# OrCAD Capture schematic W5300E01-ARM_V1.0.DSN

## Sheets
1 P1. MPU, Jtag Interface: size C; rev: 1.0
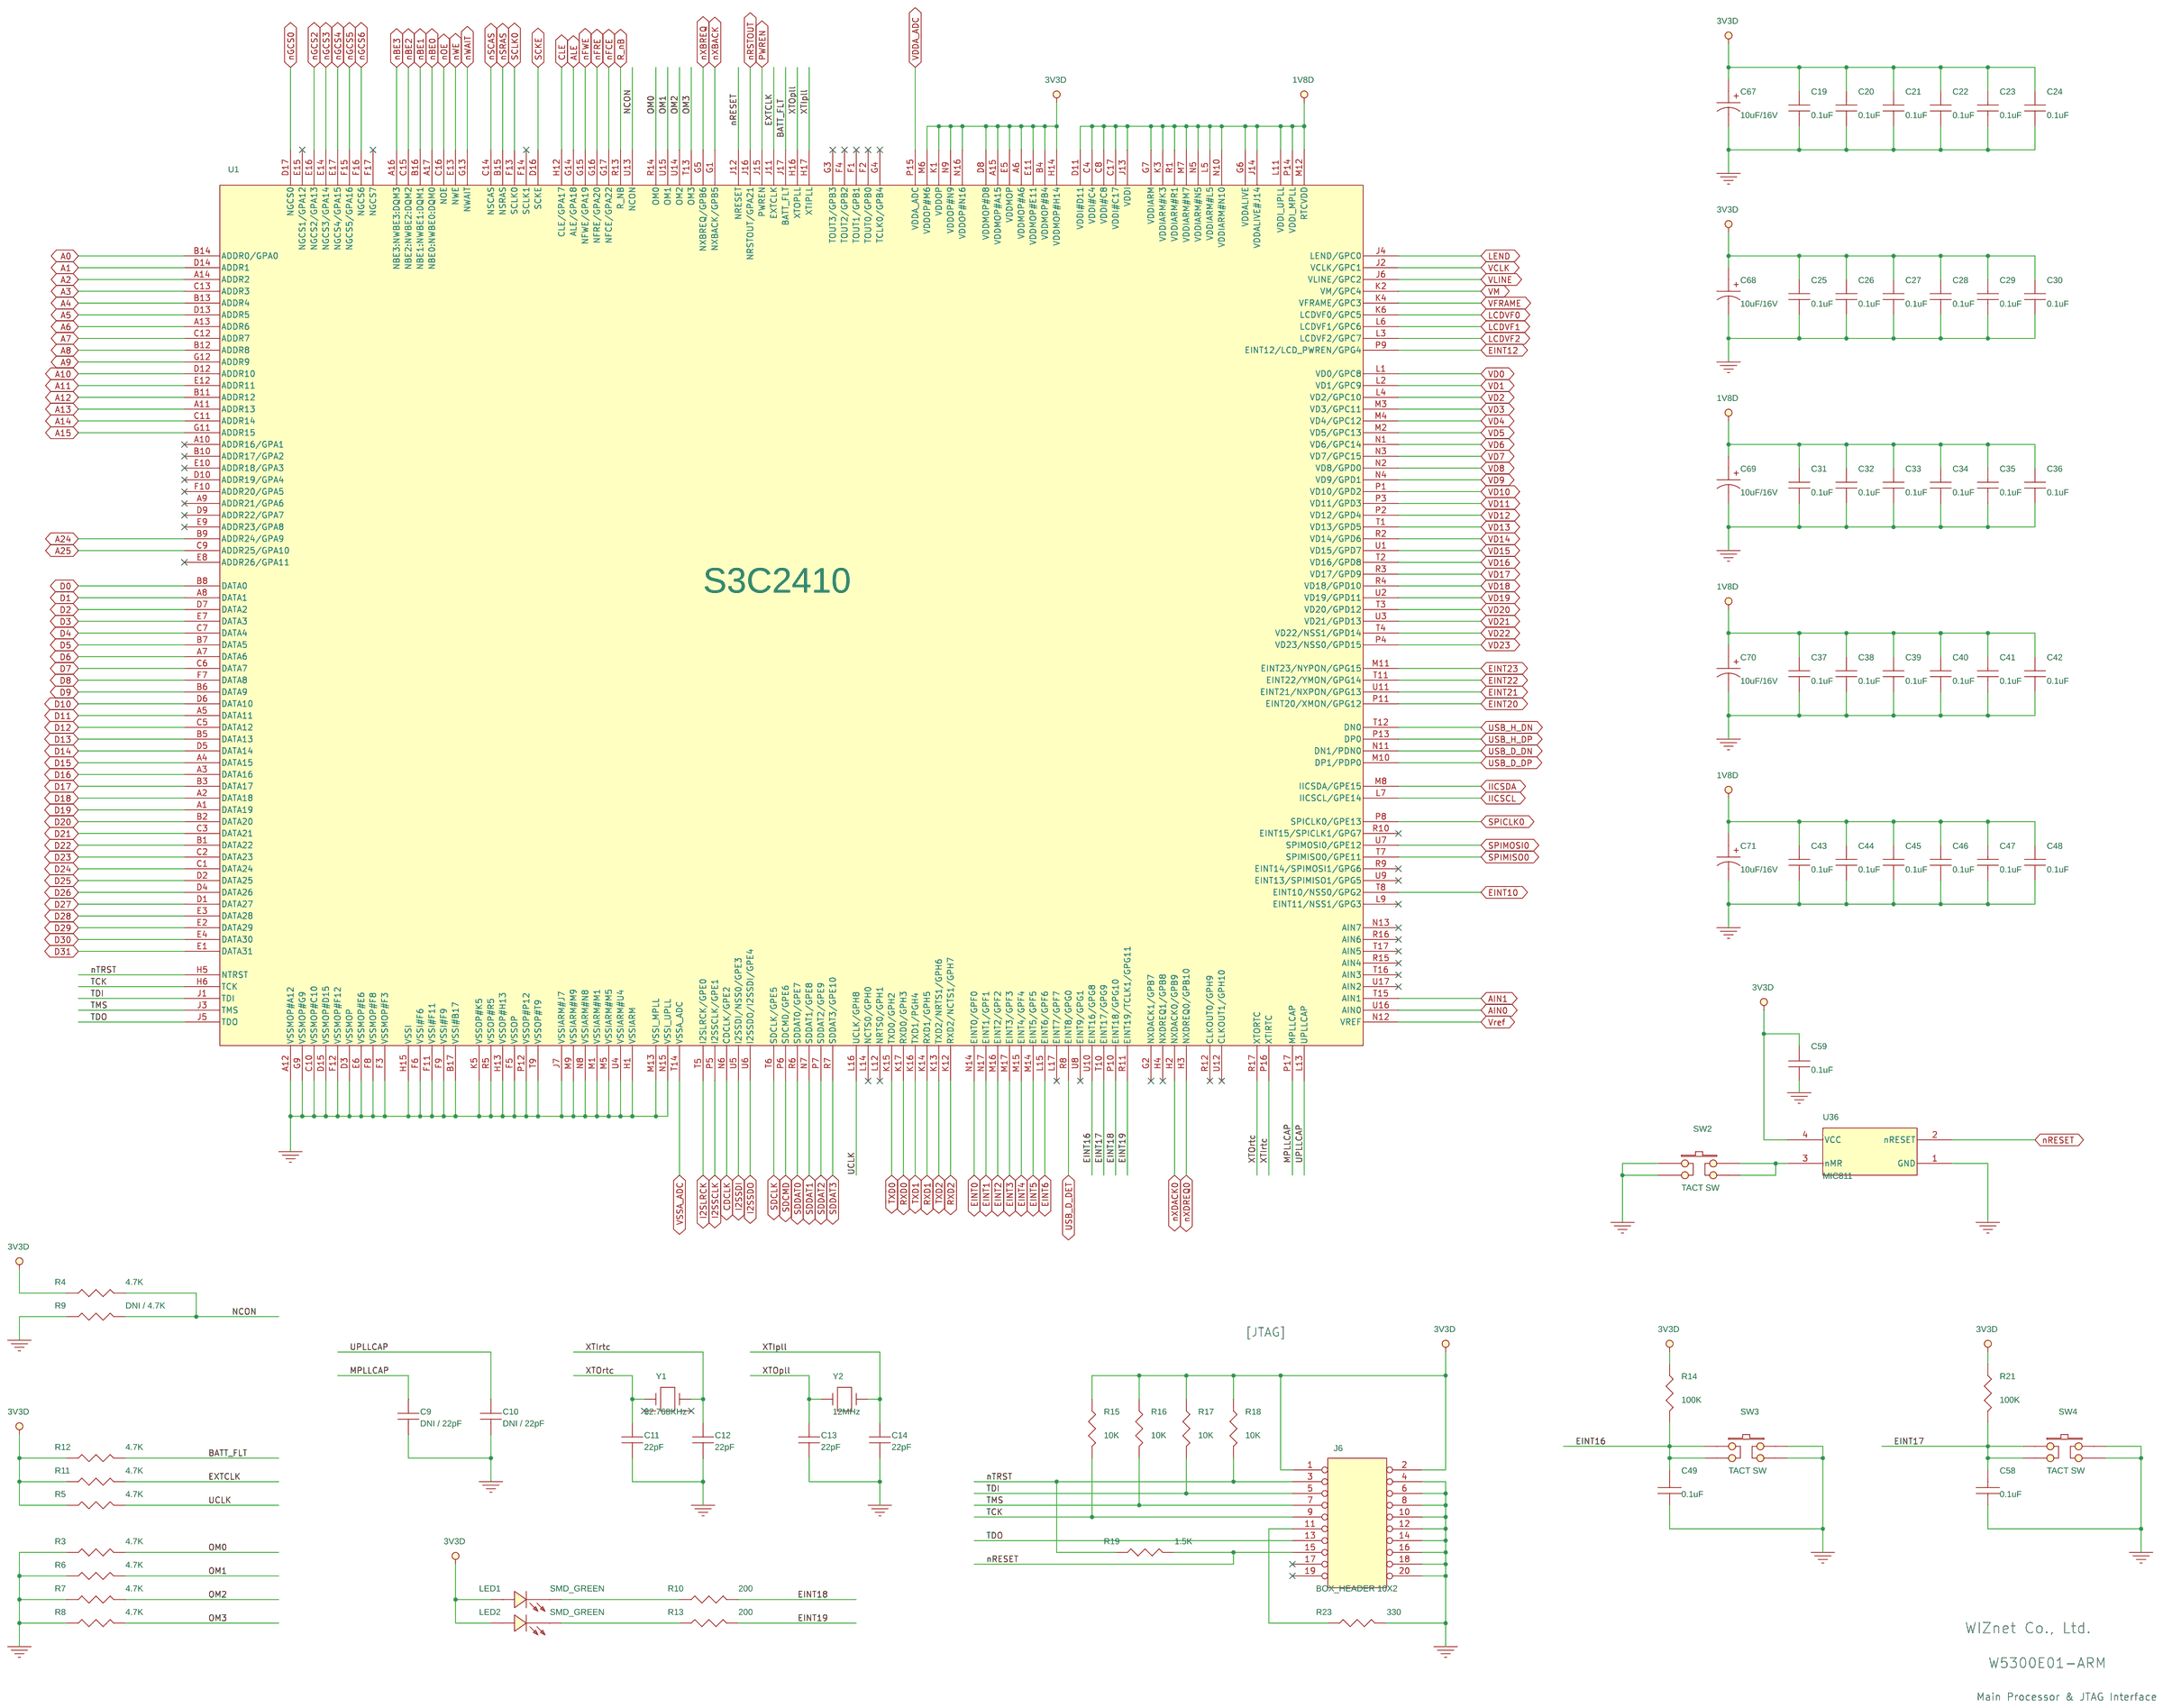
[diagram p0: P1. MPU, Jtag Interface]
2 LAYOUT
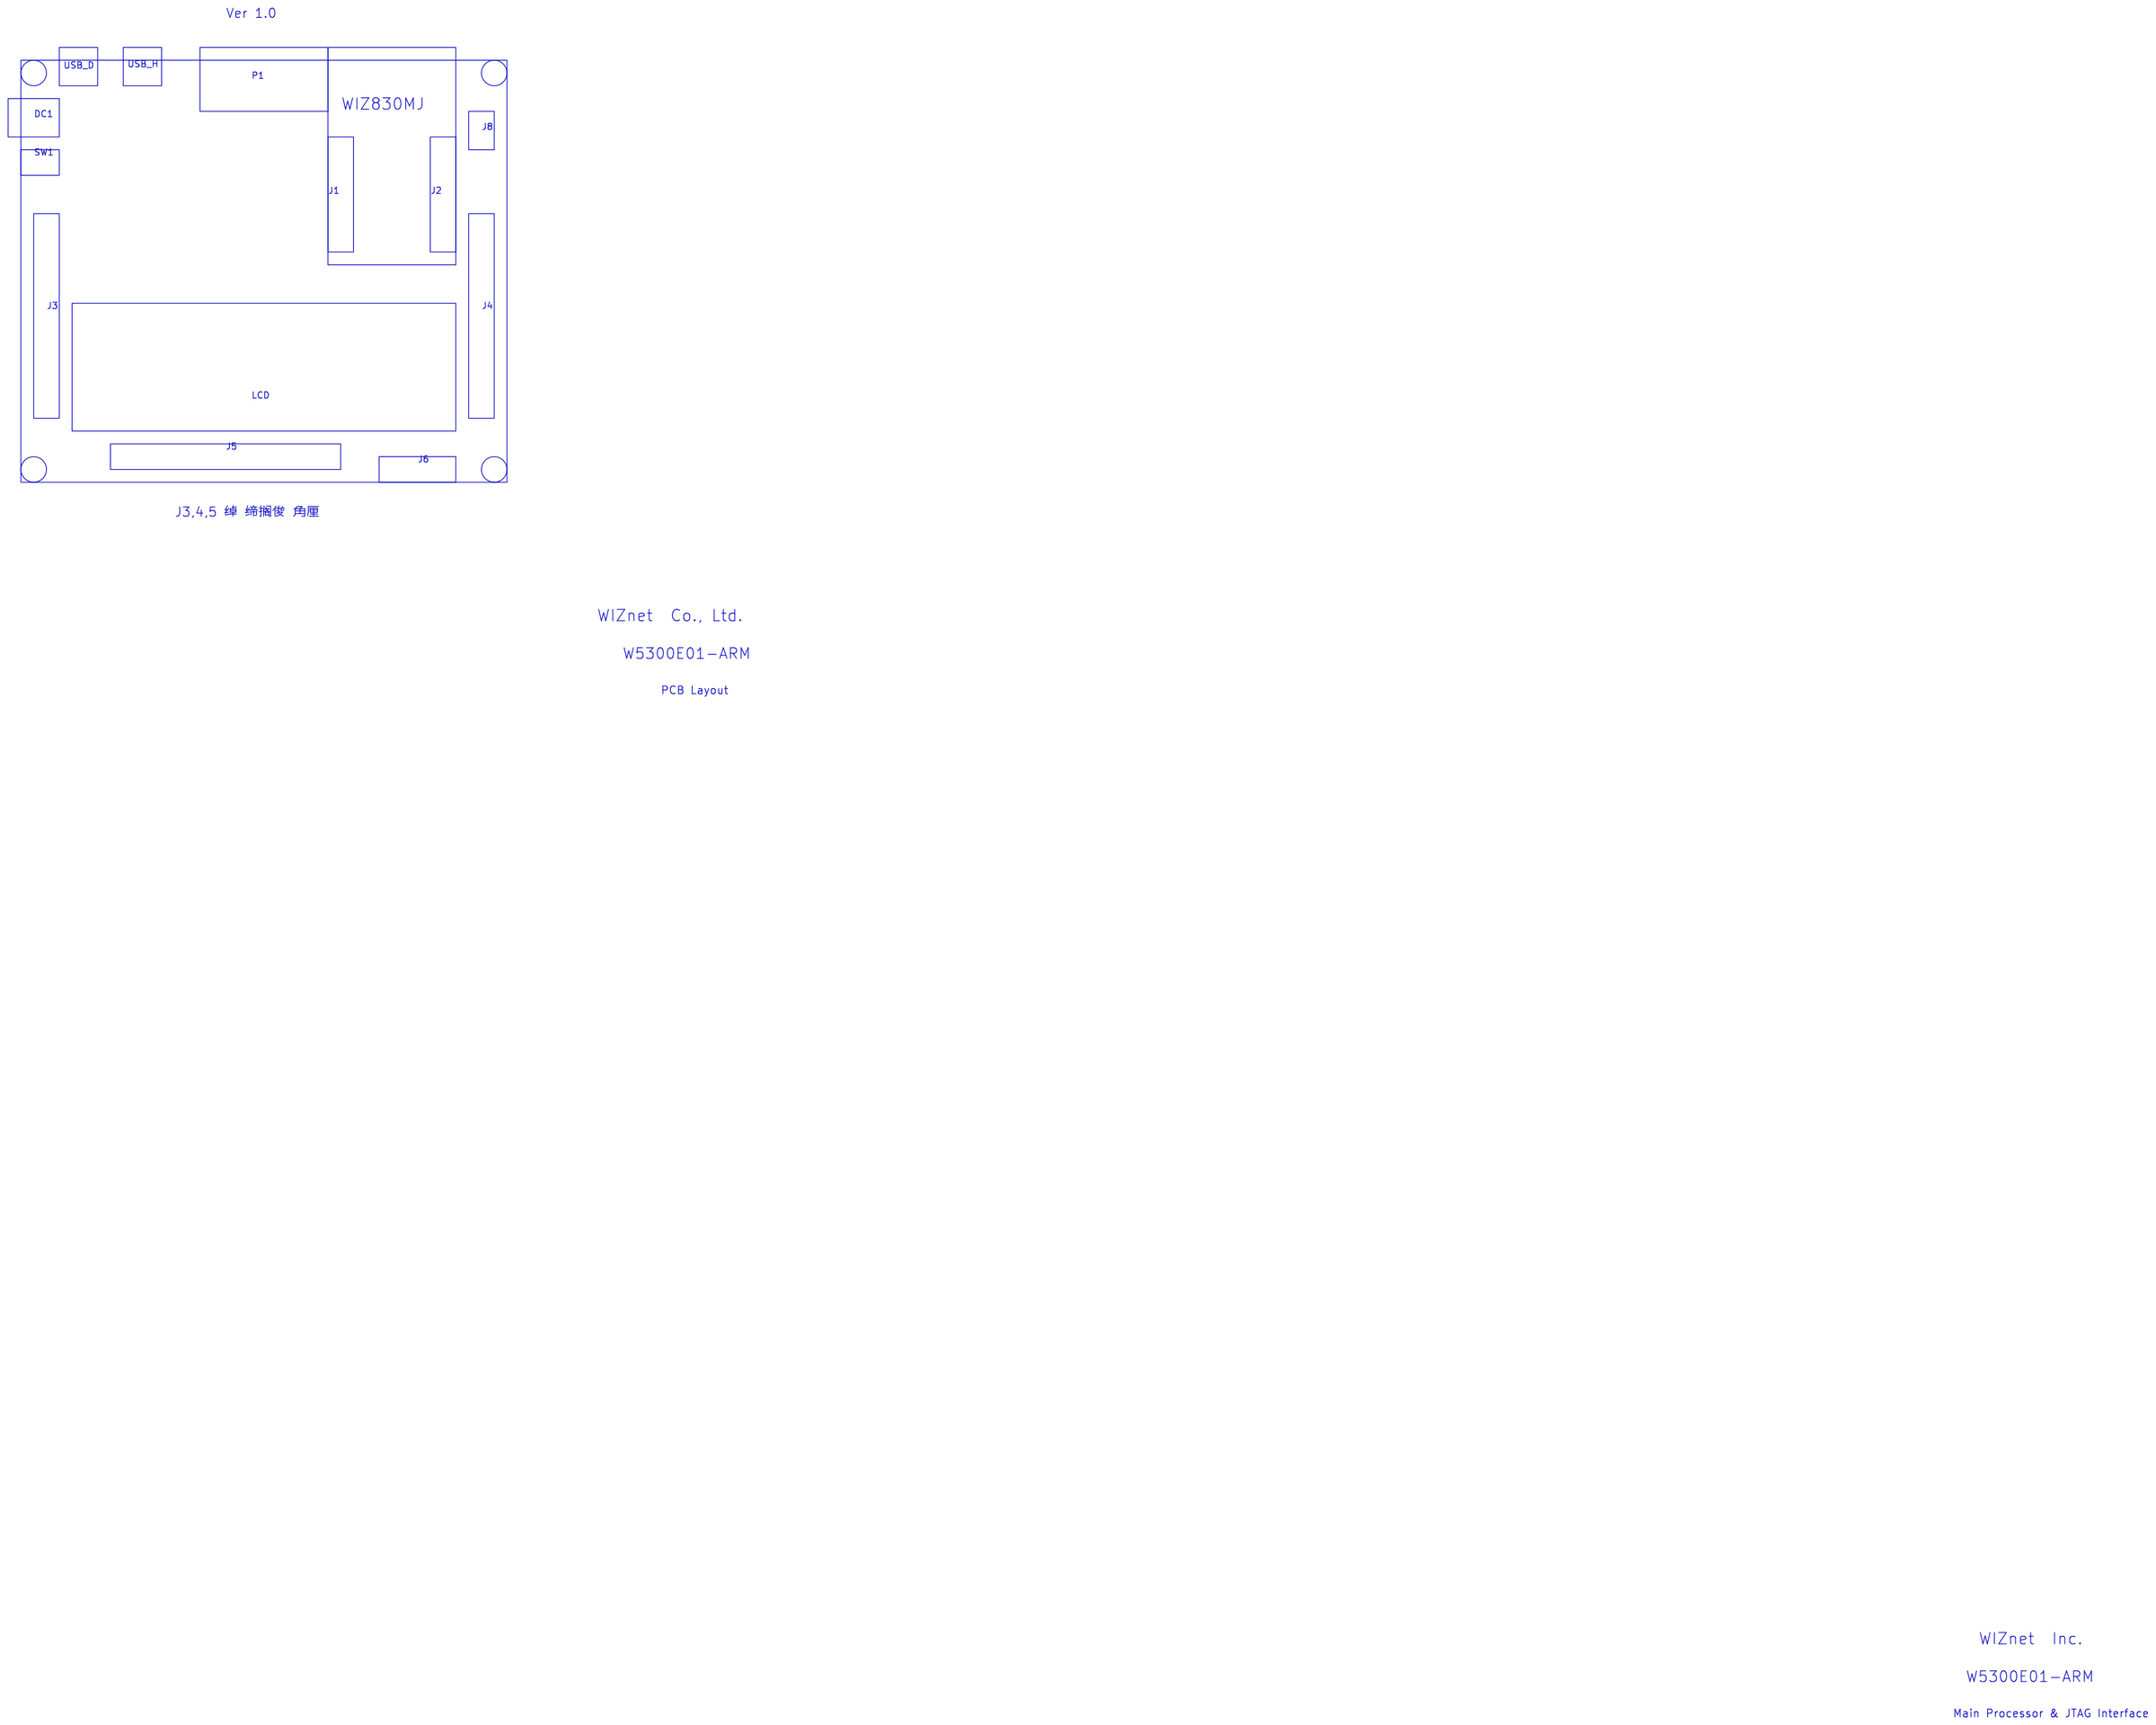
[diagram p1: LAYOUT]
3 P2. Momory, I/O, Power: size C
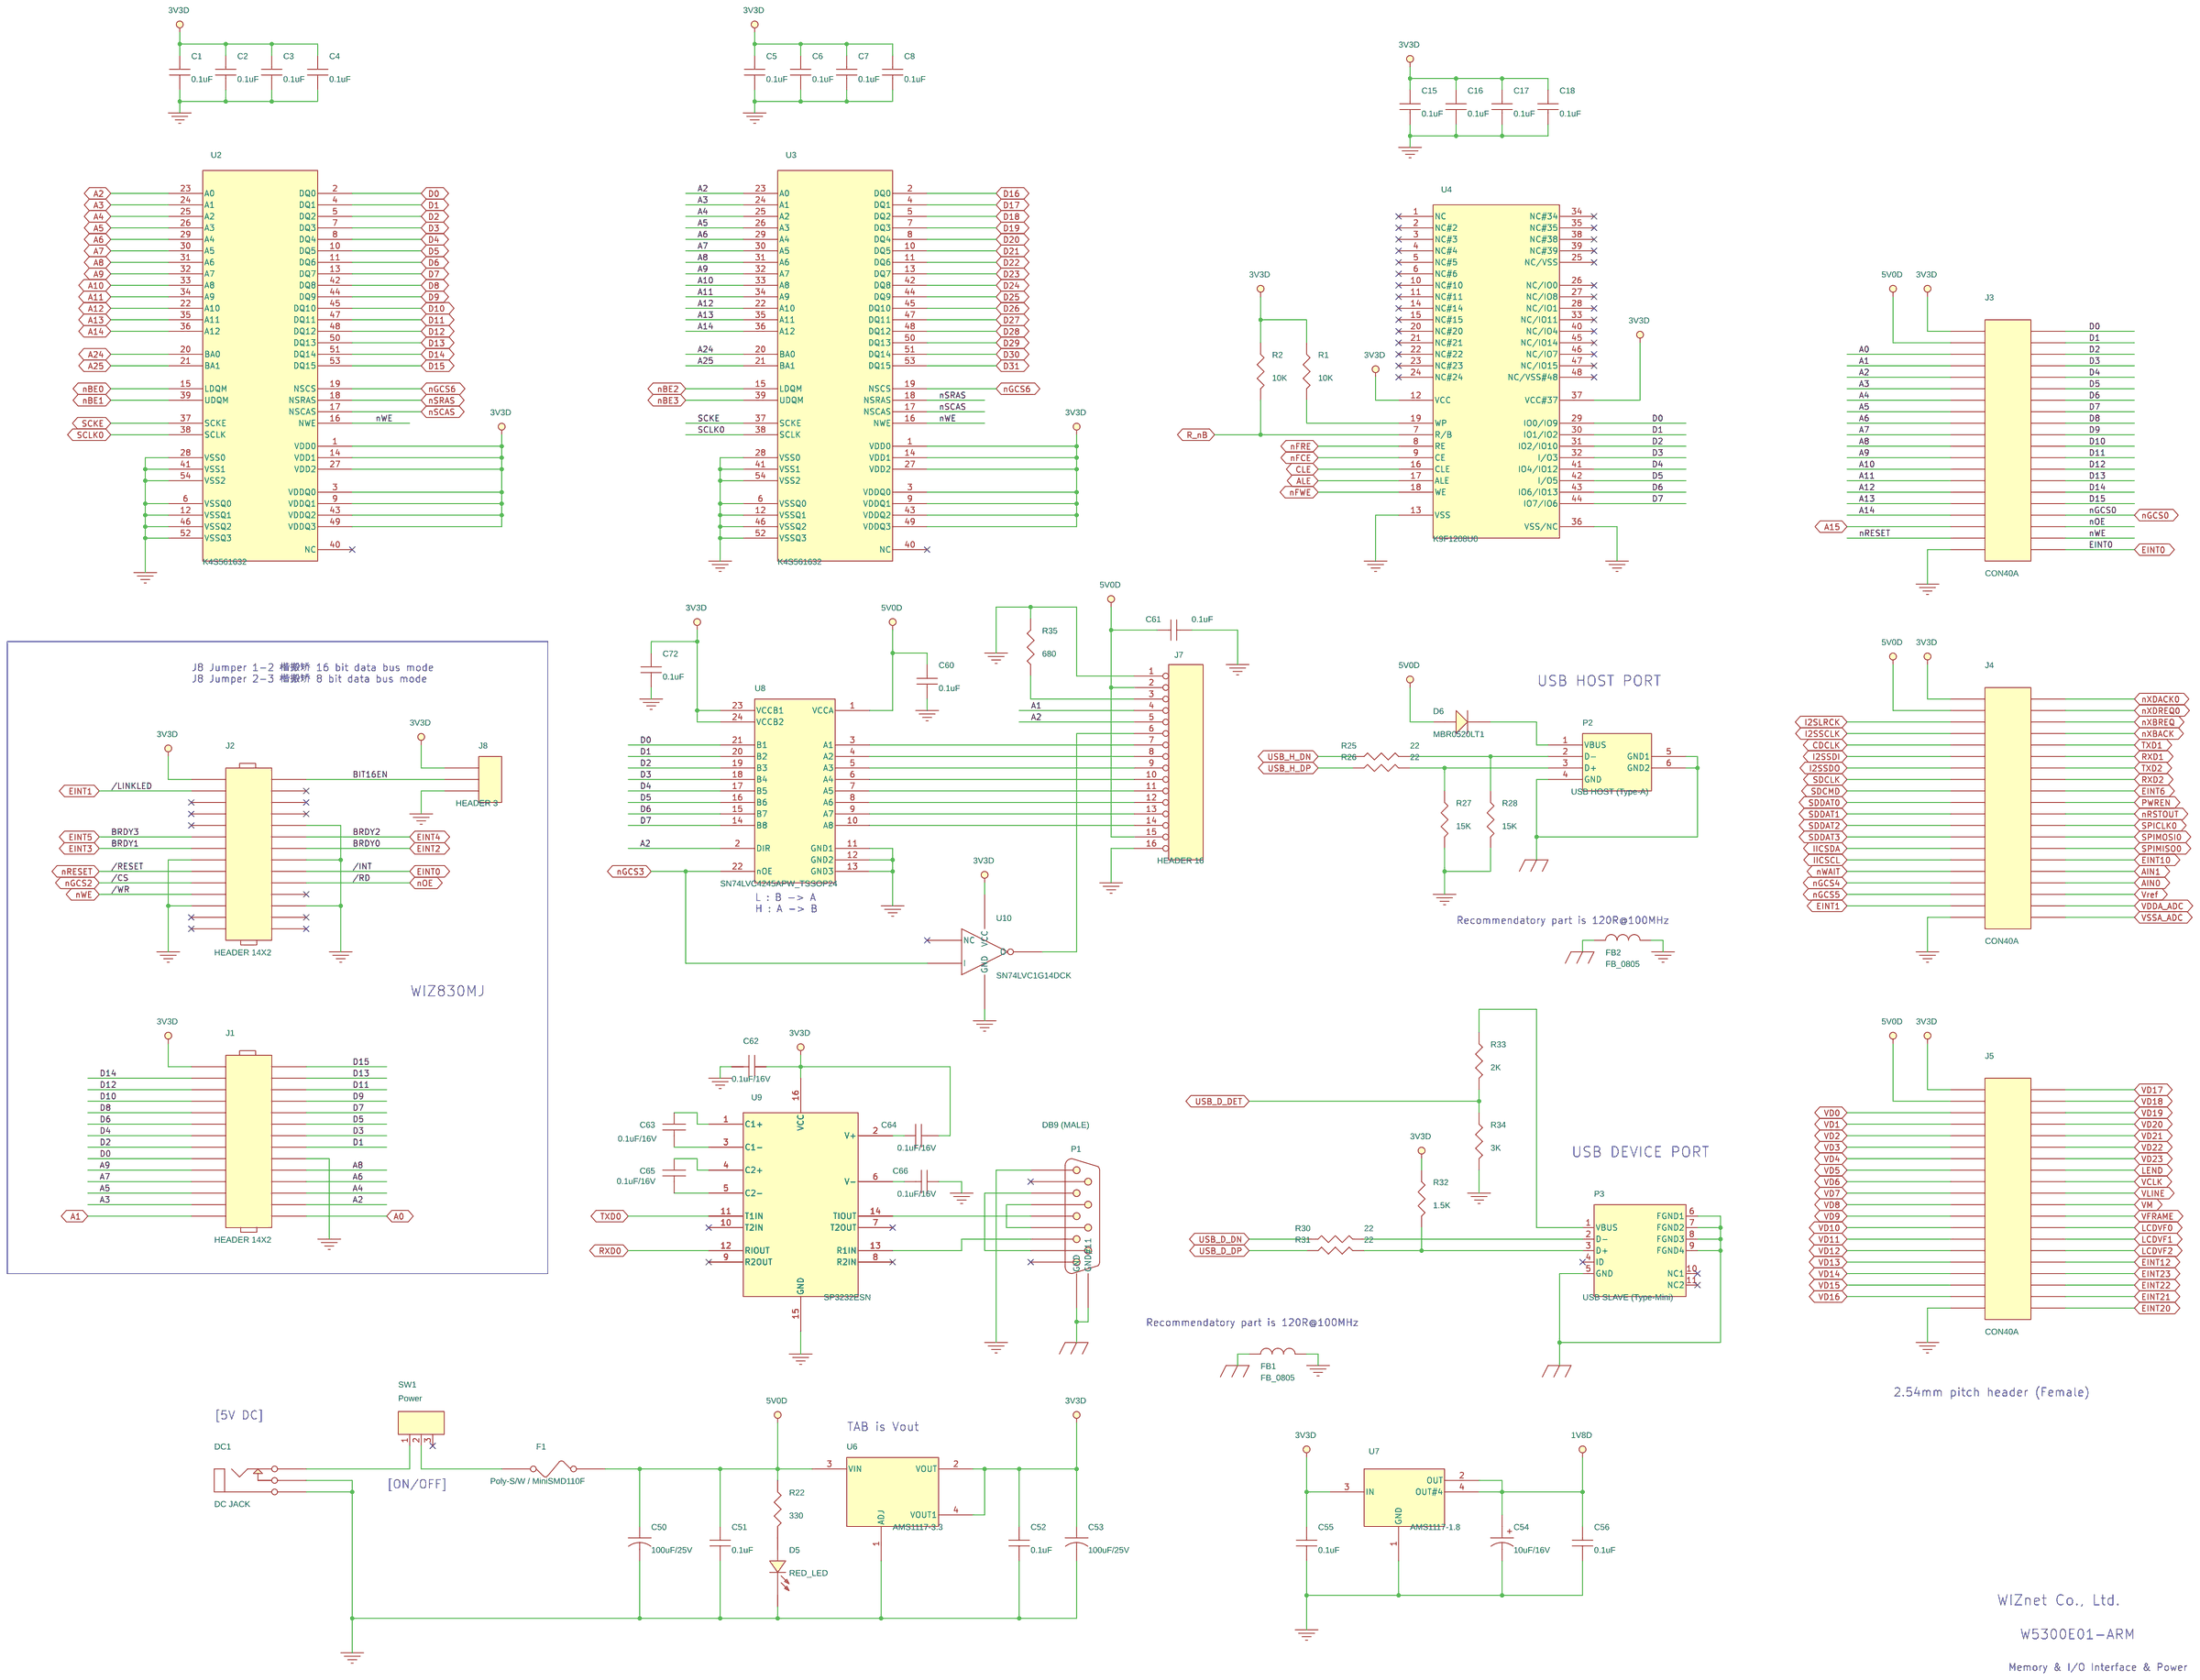
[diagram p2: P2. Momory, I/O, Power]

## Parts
sheet P1. MPU, Jtag Interface
C9  DNI / 22pF  [C0603]
C10  DNI / 22pF  [C0603]
C11  22pF  [C0603]
C12  22pF  [C0603]
C13  22pF  [C0603]
C14  22pF  [C0603]
C19  0.1uF  [C0603]
C20  0.1uF  [C0603]
C21  0.1uF  [C0603]
C22  0.1uF  [C0603]
C23  0.1uF  [C0603]
C24  0.1uF  [C0603]
C25  0.1uF  [C0603]
C26  0.1uF  [C0603]
C27  0.1uF  [C0603]
C28  0.1uF  [C0603]
C29  0.1uF  [C0603]
C30  0.1uF  [C0603]
C31  0.1uF  [C0603]
C32  0.1uF  [C0603]
C33  0.1uF  [C0603]
C34  0.1uF  [C0603]
C35  0.1uF  [C0603]
C36  0.1uF  [C0603]
C37  0.1uF  [C0603]
C38  0.1uF  [C0603]
C39  0.1uF  [C0603]
C40  0.1uF  [C0603]
C41  0.1uF  [C0603]
C42  0.1uF  [C0603]
C43  0.1uF  [C0603]
C44  0.1uF  [C0603]
C45  0.1uF  [C0603]
C46  0.1uF  [C0603]
C47  0.1uF  [C0603]
C48  0.1uF  [C0603]
C49  0.1uF  [C0603]
C58  0.1uF  [C0603]
C59  0.1uF  [C0603]
C67  10uF/16V  [CT3216]
C68  10uF/16V  [CT3216]
C69  10uF/16V  [CT3216]
C70  10uF/16V  [CT3216]
C71  10uF/16V  [CT3216]
J6  BOX_HEADER 10X2  [HS20F]
LED1  SMD_GREEN  [D0805]
LED2  SMD_GREEN  [D0805]
R3  4.7K  [R0603]
R4  4.7K  [R0603]
R5  4.7K  [R0603]
R6  4.7K  [R0603]
R7  4.7K  [R0603]
R8  4.7K  [R0603]
R9  DNI / 4.7K  [R0603]
R10  200  [R0603]
R11  4.7K  [R0603]
R12  4.7K  [R0603]
R13  200  [R0603]
R14  100K  [R0603]
R15  10K  [R0603]
R16  10K  [R0603]
R17  10K  [R0603]
R18  10K  [R0603]
R19  1.5K  [R0603]
R21  100K  [R0603]
R23  330  [R0603]
SW2  TACT SW  [TACT_SW]
SW3  TACT SW  [TACT_SW]
SW4  TACT SW  [TACT_SW]
U1  S3C2410  [S3C2410]
U36  MIC811  [sot143_a]
Y1  32.768KHz  [CS_306]
Y2  12MHz  [hc49us]
sheet P2. Momory, I/O, Power
C1  0.1uF  [C0603]
C2  0.1uF  [C0603]
C3  0.1uF  [C0603]
C4  0.1uF  [C0603]
C5  0.1uF  [C0603]
C6  0.1uF  [C0603]
C7  0.1uF  [C0603]
C8  0.1uF  [C0603]
C15  0.1uF  [C0603]
C16  0.1uF  [C0603]
C17  0.1uF  [C0603]
C18  0.1uF  [C0603]
C50  100uF/25V  [SMD_ECAP_H63]
C51  0.1uF  [C0603]
C52  0.1uF  [C0603]
C53  100uF/25V  [SMD_ECAP_H63]
C54  10uF/16V  [CT3216]
C55  0.1uF  [C0603]
C56  0.1uF  [C0603]
C60  0.1uF  [C0603]
C61  0.1uF  [C0603]
C62  0.1uF/16V  [CT3216]
C63  0.1uF/16V  [CT3216]
C64  0.1uF/16V  [CT3216]
C65  0.1uF/16V  [CT3216]
C66  0.1uF/16V  [CT3216]
C72  0.1uF  [C0603]
D5  RED_LED  [D0805]
D6  MBR0520LT1  [SOD_123]
DC1  DC JACK  [AJ210_K]
F1  Poly-S/W / MiniSMD110F  [f3216_4532]
FB1  FB_0805  [L0805]
FB2  FB_0805  [L0805]
J1  HEADER 14X2  [HS28_J1]
J2  HEADER 14X2  [HS28_J2]
J3  CON40A  [HS40]
J4  CON40A  [HS40]
J5  CON40A  [HS40]
J7  HEADER 16  [lc1624]
J8  HEADER 3  [JP3]
P1  DB9 (MALE)  [DB9M]
P2  USB HOST (Type-A)  [USB_A]
P3  USB SLAVE (Type-Mini)  [349_004_073_2]
R1  10K  [R0603]
R2  10K  [R0603]
R22  330  [R0603]
R25  22  [R0603]
R26  22  [R0603]
R27  15K  [R0603]
R28  15K  [R0603]
R30  22  [R0603]
R31  22  [R0603]
R32  1.5K  [R0603]
R33  2K  [R0603]
R34  3K  [R0603]
R35  680  [R0603]
SW1  Power  [sw3_100m_h35]
U2  K4S561632  [K4S281632]
U3  K4S561632  [K4S281632]
U4  K9F1208U0  [TSOP48PIN_1220F]
U6  AMS1117-3.3  [SOT223_4]
U7  AMS1117-1.8  [SOT223_4]
U8  SN74LVC4245APW_TSSOP24  [tssop24]
U9  SP3232ESN  [soic16_150mil]
U10  SN74LVC1G14DCK  [sot323-5]

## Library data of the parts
C1-C48 C51 C52 C59-C61 C72 = CAP_NP
C49 = C_0: TYPE: 1608_SIZE
C58 = C_1: TYPE: 1608_SIZE
C67-C71 = CAPACITOR_POL
J6 = HEADER_10X2
LED1 LED2 = LED_0: TYPE: 1608_SIZE
R1-R19 R21-R23 R25-R28 R30-R35 = R
SW2-SW4 = SW_PUSHBUTTON-SPST-2_0
U1 = S3C2410_2
U36 = MAX811TEUS_0
Y1 = CRYSTAL_0
Y2 = CRYSTAL
C50 C53 = CAP_0
C54 = CAPACITOR_POL_1
C55 = CAP_NP_1
C56 = CAP_NP_2
C62 = C_6
C63 = C_2
C64 = C_4
C65 = C_3
C66 = C_5
D5 = LED_0
D6 = DIODE_0
DC1 = PHONEJACK_0
F1 = FUSE
FB1 FB2 = FB_0805
J1 J2 = HEADER_14X2
J3-J5 = CON40A
J7 = HEADER_16
J8 = CON3
P1 = CONNECTOR_DB9_1
P2 = USBPORT_2
P3 = CON5_2
SW1 = CON3_v2
U2 U3 = K4S561632C-TC75_1
U4 = K9F1208U0A_0
U6 = LM317S_2
U7 = LM1117A-1_0.8V
U8 = 74ACT573_1
U9 = SP232A_1
U10 = TC7SL04FU_0

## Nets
1V8D: C31.1 C32.1 C33.1 C34.1 C35.1 C36.1 C37.1 C38.1 C39.1 C40.1 C41.1 C42.1 C43.1 C44.1 C45.1 C46.1 C47.1 C48.1 C54.1 C56.1 C69.1 C70.1 C71.1 U1.C4(VDDI#C4) U1.C8(VDDI#C8) U1.C17(VDDI#C17) U1.D11(VDDI#D11) U1.G6(VDDALIVE) U1.G7(VDDIARM) U1.J13(VDDI) U1.J14(VDDALIVE#J14) U1.K3(VDDIARM#K3) U1.L5(VDDIARM#L5) U1.L11(VDDI_UPLL) U1.M7(VDDIARM#M7) U1.M12(RTCVDD) U1.N5(VDDIARM#N5) U1.N10(VDDIARM#N10) U1.P14(VDDI_MPLL) U1.R1(VDDIARM#R1) U7.2(OUT) U7.4(OUT#4)
3V3D: C1.1 C2.1 C3.1 C4.1 C5.1 C6.1 C7.1 C8.1 C15.1 C16.1 C17.1 C18.1 C19.1 C20.1 C21.1 C22.1 C23.1 C24.1 C25.1 C26.1 C27.1 C28.1 C29.1 C30.1 C52.1 C53.1 C55.1 C59.2 C62.1 C64.2 C67.1 C68.1 C72.1 J1.1 J2.1 J3.1 J4.1 J5.1 J6.1 J6.2 J8.1 LED1.2(ANODE) LED2.2(ANODE) R1.1 R2.1 R4.1 R5.1 R11.1 R12.1 R14.1 R15.1 R16.1 R17.1 R18.1 R21.1 R32.1 U1.A6(VDDMOP#A6) U1.A15(VDDMOP#A15) U1.B4(VDDMOP#B4) U1.D8(VDDMOP#D8) U1.E5(VDDMOP) U1.E11(VDDMOP#E11) U1.H14(VDDMOP#H14) U1.K1(VDDOP) U1.M6(VDDOP#M6) U1.N9(VDDOP#N9) U1.N16(VDDOP#N16) U2.1(VDD0) U2.3(VDDQ0) U2.9(VDDQ1) U2.14(VDD1) U2.27(VDD2) U2.43(VDDQ2) U2.49(VDDQ3) U3.1(VDD0) U3.3(VDDQ0) U3.9(VDDQ1) U3.14(VDD1) U3.27(VDD2) U3.43(VDDQ2) U3.49(VDDQ3) U4.12(VCC) U4.37(VCC#37) U6.2(VOUT) U6.4(VOUT1) U7.3(IN) U8.23(VCCB1) U8.24(VCCB2) U9.16(VCC) U10.5(VCC) U36.4(VCC)
5V0D: C50.1 C51.1 C60.1 C61.1 D6.2 F1.1 J3.3 J4.3 J5.3 J7.2 J7.15 R22.1 U6.3(VIN) U8.1(VCCA)
GND: C1.2 C2.2 C3.2 C4.2 C5.2 C6.2 C7.2 C8.2 C9.2 C10.2 C11.2 C12.2 C13.2 C14.2 C15.2 C16.2 C17.2 C18.2 C19.2 C20.2 C21.2 C22.2 C23.2 C24.2 C25.2 C26.2 C27.2 C28.2 C29.2 C30.2 C31.2 C32.2 C33.2 C34.2 C35.2 C36.2 C37.2 C38.2 C39.2 C40.2 C41.2 C42.2 C43.2 C44.2 C45.2 C46.2 C47.2 C48.2 C49.1 C50.2 C51.2 C52.2 C53.2 C54.2 C55.2 C56.2 C58.1 C59.1 C60.2 C61.2 C62.2 C66.1 C67.2 C68.2 C69.2 C70.2 C71.2 C72.2 D5.1(CATHODE) DC1.2 DC1.3 FB1.2 FB2.2 J1.18 J2.10 J2.15 J2.16 J2.23 J2.24 J3.39 J4.39 J5.39 J6.4 J6.6 J6.8 J6.10 J6.12 J6.14 J6.16 J6.18 J6.20 J7.1 J7.16 J8.3 P1.5 R3.1 R6.1 R7.1 R8.1 R9.1 R23.2 R27.2 R28.2 R34.2 R35.2 SW2.1 SW2.4 SW3.2 SW3.3 SW4.2 SW4.3 U1.A12(VSSMOP#A12) U1.B17(VSSI#B17) U1.C10(VSSMOP#C10) U1.D3(VSSMOP) U1.D15(VSSMOP#D15) U1.E6(VSSMOP#E6) U1.F3(VSSMOP#F3) U1.F5(VSSOP) U1.F6(VSSI#F6) U1.F8(VSSMOP#F8) U1.F9(VSSI#F9) U1.F11(VSSI#F11) U1.F12(VSSMOP#F12) U1.G9(VSSMOP#G9) U1.H1(VSSIARM) U1.H13(VSSOP#H13) U1.H15(VSSI) U1.J7(VSSIARM#J7) U1.K5(VSSOP#K5) U1.M1(VSSIARM#M1) U1.M5(VSSIARM#M5) U1.M9(VSSIARM#M9) U1.M13(VSSI_MPLL) U1.N8(VSSIARM#N8) U1.N15(VSSI_UPLL) U1.P12(VSSOP#P12) U1.R5(VSSOP#R5) U1.T9(VSSOP#T9) U1.U4(VSSIARM#U4) U2.6(VSSQ0) U2.12(VSSQ1) U2.28(VSS0) U2.41(VSS1) U2.46(VSSQ2) U2.52(VSSQ3) U2.54(VSS2) U3.6(VSSQ0) U3.12(VSSQ1) U3.28(VSS0) U3.41(VSS1) U3.46(VSSQ2) U3.52(VSSQ3) U3.54(VSS2) U4.13(VSS) U4.36(VSS/NC) U6.1(ADJ) U7.1(GND) U8.11(GND1) U8.12(GND2) U8.13(GND3) U9.15(GND) U10.3(GND) U36.1(GND)
GND_EARTH: FB1.1 FB2.1 P1.10(GND) P1.11(GND#11) P2.4(GND) P2.5(GND1) P2.6(GND2) P3.5(GND) P3.6(FGND1) P3.7(FGND2) P3.8(FGND3) P3.9(FGND4)
VDDA_ADC: J4.38 U1.P15(VDDA_ADC)
VSSA_ADC: J4.40 U1.T14(VSSA_ADC)
A0: J1.28 J3.5 U1.B14(ADDR0/GPA0)
A1: J1.27 J3.7 J7.4 U1.D14(ADDR1)
A2: J1.26 J3.9 J7.5 U1.A14(ADDR2) U2.23(A0) U3.23(A0) U8.2(DIR)
A3: J1.25 J3.11 U1.C13(ADDR3) U2.24(A1) U3.24(A1)
A4: J1.24 J3.13 U1.B13(ADDR4) U2.25(A2) U3.25(A2)
A5: J1.23 J3.15 U1.D13(ADDR5) U2.26(A3) U3.26(A3)
A6: J1.22 J3.17 U1.A13(ADDR6) U2.29(A4) U3.29(A4)
A7: J1.21 J3.19 U1.C12(ADDR7) U2.30(A5) U3.30(A5)
A8: J1.20 J3.21 U1.B12(ADDR8) U2.31(A6) U3.31(A6)
A9: J1.19 J3.23 U1.G12(ADDR9) U2.32(A7) U3.32(A7)
A10: J3.25 U1.D12(ADDR10) U2.33(A8) U3.33(A8)
A11: J3.27 U1.E12(ADDR11) U2.34(A9) U3.34(A9)
A12: J3.29 U1.B11(ADDR12) U2.22(A10) U3.22(A10)
A13: J3.31 U1.A11(ADDR13) U2.35(A11) U3.35(A11)
A14: J3.33 U1.C11(ADDR14) U2.36(A12) U3.36(A12)
A15: J3.35 U1.G11(ADDR15)
A24: U1.B9(ADDR24/GPA9) U2.20(BA0) U3.20(BA0)
A25: U1.C9(ADDR25/GPA10) U2.21(BA1) U3.21(BA1)
AIN0: J4.34 U1.U16(AIN0)
AIN1: J4.32 U1.T15(AIN1)
ALE: U1.G14(ALE/GPA18) U4.17(ALE)
BATT_FLT: R12.2 U1.J17(BATT_FLT)
BIT16EN: J2.2 J8.2
CDCLK: J4.9 U1.N6(CDCLK/GPE2)
CLE: U1.H12(CLE/GPA17) U4.16(CLE)
D0: J1.17 J3.2 U1.B8(DATA0) U2.2(DQ0) U4.29(IO0/IO9) U8.21(B1)
D1: J1.16 J3.4 U1.A8(DATA1) U2.4(DQ1) U4.30(IO1/IO2) U8.20(B2)
D2: J1.15 J3.6 U1.D7(DATA2) U2.5(DQ2) U4.31(IO2/IO10) U8.19(B3)
D3: J1.14 J3.8 U1.E7(DATA3) U2.7(DQ3) U4.32(I/O3) U8.18(B4)
D4: J1.13 J3.10 U1.C7(DATA4) U2.8(DQ4) U4.41(IO4/IO12) U8.17(B5)
D5: J1.12 J3.12 U1.B7(DATA5) U2.10(DQ5) U4.42(I/O5) U8.16(B6)
D6: J1.11 J3.14 U1.A7(DATA6) U2.11(DQ6) U4.43(IO6/IO13) U8.15(B7)
D7: J1.10 J3.16 U1.C6(DATA7) U2.13(DQ7) U4.44(IO7/IO6) U8.14(B8)
D8: J1.9 J3.18 U1.F7(DATA8) U2.42(DQ8)
D9: J1.8 J3.20 U1.B6(DATA9) U2.44(DQ9)
D10: J1.7 J3.22 U1.D6(DATA10) U2.45(DQ10)
D11: J1.6 J3.24 U1.A5(DATA11) U2.47(DQ11)
D12: J1.5 J3.26 U1.C5(DATA12) U2.48(DQ12)
D13: J1.4 J3.28 U1.B5(DATA13) U2.50(DQ13)
D14: J1.3 J3.30 U1.D5(DATA14) U2.51(DQ14)
D15: J1.2 J3.32 U1.A4(DATA15) U2.53(DQ15)
D16: U1.A3(DATA16) U3.2(DQ0)
D17: U1.B3(DATA17) U3.4(DQ1)
D18: U1.A2(DATA18) U3.5(DQ2)
D19: U1.A1(DATA19) U3.7(DQ3)
D20: U1.B2(DATA20) U3.8(DQ4)
D21: U1.C3(DATA21) U3.10(DQ5)
D22: U1.B1(DATA22) U3.11(DQ6)
D23: U1.C2(DATA23) U3.13(DQ7)
D24: U1.C1(DATA24) U3.42(DQ8)
D25: U1.D2(DATA25) U3.44(DQ9)
D26: U1.D4(DATA26) U3.45(DQ10)
D27: U1.D1(DATA27) U3.47(DQ11)
D28: U1.E3(DATA28) U3.48(DQ12)
D29: U1.E2(DATA29) U3.50(DQ13)
D30: U1.E4(DATA30) U3.51(DQ14)
D31: U1.E1(DATA31) U3.53(DQ15)
EINT0: J2.18 J3.40 U1.N14(EINT0/GPF0)
EINT1: J2.3 J4.37 U1.N17(EINT1/GPF1)
EINT2: J2.14 U1.M16(EINT2/GPF2)
EINT3: J2.13 U1.M17(EINT3/GPF3)
EINT4: J2.12 U1.M15(EINT4/GPF4)
EINT5: J2.11 U1.M14(EINT5/GPF5)
EINT6: J4.18 U1.L15(EINT6/GPF6)
EINT10: J4.30 U1.T8(EINT10/NSS0/GPG2)
EINT12: J5.32 U1.P9(EINT12/LCD_PWREN/GPG4)
EINT16: C49.2 R14.2 SW3.1 SW3.4 U1.U10(EINT16/GPG8)
EINT17: C58.2 R21.2 SW4.1 SW4.4 U1.T10(EINT17/GPG9)
EINT18: R10.2 U1.P10(EINT18/GPG10)
EINT19: R13.2 U1.R11(EINT19/TCLK1/GPG11)
EINT20: J5.40 U1.P11(EINT20/XMON/GPG12)
EINT21: J5.38 U1.U11(EINT21/NXPON/GPG13)
EINT22: J5.36 U1.T11(EINT22/YMON/GPG14)
EINT23: J5.34 U1.M11(EINT23/NYPON/GPG15)
EXTCLK: R11.2 U1.J11(EXTCLK)
I2SLRCK: J4.5 U1.T5(I2SLRCK/GPE0)
I2SSCLK: J4.7 U1.P5(I2SSCLK/GPE1)
I2SSDI: J4.11 U1.U5(I2SSDI/NSS0/GPE3)
I2SSDO: J4.13 U1.U6(I2SSDO/I2SSDI/GPE4)
IICSCL: J4.29 U1.L7(IICSCL/GPE14)
IICSDA: J4.27 U1.M8(IICSDA/GPE15)
LCDVF0: J5.26 U1.K6(LCDVF0/GPC5)
LCDVF1: J5.28 U1.L6(LCDVF1/GPC6)
LCDVF2: J5.30 U1.L3(LCDVF2/GPC7)
LEND: J5.16 U1.J4(LEND/GPC0)
MPLLCAP: C9.1 U1.P17(MPLLCAP)
nBE0: U1.A17(NBE0:NWBE0:DQM0) U2.15(LDQM)
nBE1: U1.B16(NBE1:NWBE1:DQM1) U2.39(UDQM)
nBE2: U1.C15(NBE2:NWBE2:DQM2) U3.15(LDQM)
nBE3: U1.A16(NBE3:NWBE3:DQM3) U3.39(UDQM)
NCON: R4.2 R9.2 U1.U13(NCON)
nFCE: U1.G17(NFCE/GPA22) U4.9(CE)
nFRE: U1.G16(NFRE/GPA20) U4.8(RE)
nFWE: U1.G15(NFWE/GPA19) U4.18(WE)
nGCS0: J3.34 U1.D17(NGCS0)
nGCS2: J2.19 U1.E16(NGCS2/GPA13)
nGCS3: U1.E14(NGCS3/GPA14) U8.22(nOE) U10.2(I)
nGCS4: J4.33 U1.E17(NGCS4/GPA15)
nGCS5: J4.35 U1.F15(NGCS5/GPA16)
nGCS6: U1.F16(NGCS6) U2.19(NSCS) U3.19(NSCS)
nOE: J2.20 J3.36 U1.C16(NOE)
nRESET: J2.17 J3.37 J6.15 R19.2 U1.J12(NRESET) U36.2(nRESET)
nRSTOUT: J4.22 U1.J16(NRSTOUT/GPA21)
nSCAS: U1.C14(NSCAS) U2.17(NSCAS) U3.17(NSCAS)
nSRAS: U1.B15(NSRAS) U2.18(NSRAS) U3.18(NSRAS)
nTRST: J6.3 R18.2 R19.1 U1.H5(NTRST)
nWAIT: J4.31 U1.G13(NWAIT)
nWE: J2.21 J3.38 U1.E13(NWE) U2.16(NWE) U3.16(NWE)
nXBACK: J4.8 U1.G1(NXBACK/GPB5)
nXBREQ: J4.6 U1.G5(NXBREQ/GPB6)
nXDACK0: J4.2 U1.H2(NXDACK0/GPB9)
nXDREQ0: J4.4 U1.H3(NXDREQ0/GPB10)
OM0: R3.2 U1.R14(OM0)
OM1: R6.2 U1.U15(OM1)
OM2: R7.2 U1.U14(OM2)
OM3: R8.2 U1.T13(OM3)
PWREN: J4.20 U1.J15(PWREN)
R_nB: R2.2 U1.R13(R_NB) U4.7(R/B)
RXD0: U1.K17(RXD0/GPH3) U9.12(RIOUT)
RXD1: J4.12 U1.K14(RXD1/GPH5)
RXD2: J4.16 U1.K12(RXD2/NCTS1/GPH7)
SCKE: U1.D16(SCKE) U2.37(SCKE) U3.37(SCKE)
SCLK0: U1.F13(SCLK0) U2.38(SCLK) U3.38(SCLK)
SDCLK: J4.15 U1.T6(SDCLK/GPE5)
SDCMD: J4.17 U1.P6(SDCMD/GPE6)
SDDAT0: J4.19 U1.R6(SDDAT0/GPE7)
SDDAT1: J4.21 U1.N7(SDDAT1/GPE8)
SDDAT2: J4.23 U1.P7(SDDAT2/GPE9)
SDDAT3: J4.25 U1.R7(SDDAT3/GPE10)
SPICLK0: J4.24 U1.P8(SPICLK0/GPE13)
SPIMISO0: J4.28 U1.T7(SPIMISO0/GPE11)
SPIMOSI0: J4.26 U1.U7(SPIMOSI0/GPE12)
TCK: J6.9 R15.2 U1.H6(TCK)
TDI: J6.5 R17.2 U1.J1(TDI)
TDO: J6.13 U1.J5(TDO)
TMS: J6.7 R16.2 U1.J3(TMS)
TXD0: U1.K15(TXD0/GPH2) U9.11(T1IN)
TXD1: J4.10 U1.K16(TXD1/PGH4)
TXD2: J4.14 U1.K13(TXD2/NRTS1/GPH6)
UCLK: R5.2 U1.L16(UCLK/GPH8)
UPLLCAP: C10.1 U1.L13(UPLLCAP)
USB_D_DET: R33.2 R34.1 U1.R8(EINT8/GPG0)
USB_D_DN: R30.1 U1.N11(DN1/PDN0)
USB_D_DP: R31.1 U1.M10(DP1/PDP0)
USB_H_DN: R25.1 U1.T12(DN0)
USB_H_DP: R26.1 U1.P13(DP0)
VCLK: J5.18 U1.J2(VCLK/GPC1)
VD0: J5.5 U1.L1(VD0/GPC8)
VD1: J5.7 U1.L2(VD1/GPC9)
VD2: J5.9 U1.L4(VD2/GPC10)
VD3: J5.11 U1.M3(VD3/GPC11)
VD4: J5.13 U1.M4(VD4/GPC12)
VD5: J5.15 U1.M2(VD5/GPC13)
VD6: J5.17 U1.N1(VD6/GPC14)
VD7: J5.19 U1.N3(VD7/GPC15)
VD8: J5.21 U1.N2(VD8/GPD0)
VD9: J5.23 U1.N4(VD9/GPD1)
VD10: J5.25 U1.P1(VD10/GPD2)
VD11: J5.27 U1.P3(VD11/GPD3)
VD12: J5.29 U1.P2(VD12/GPD4)
VD13: J5.31 U1.T1(VD13/GPD5)
VD14: J5.33 U1.R2(VD14/GPD6)
VD15: J5.35 U1.U1(VD15/GPD7)
VD16: J5.37 U1.T2(VD16/GPD8)
VD17: J5.2 U1.R3(VD17/GPD9)
VD18: J5.4 U1.R4(VD18/GPD10)
VD19: J5.6 U1.U2(VD19/GPD11)
VD20: J5.8 U1.T3(VD20/GPD12)
VD21: J5.10 U1.U3(VD21/GPD13)
VD22: J5.12 U1.T4(VD22/NSS1/GPD14)
VD23: J5.14 U1.P4(VD23/NSS0/GPD15)
VFRAME: J5.24 U1.K4(VFRAME/GPC3)
VLINE: J5.20 U1.J6(VLINE/GPC2)
VM: J5.22 U1.K2(VM/GPC4)
Vref: J4.36 U1.N12(VREF)
XTIpll: C14.1 U1.H17(XTIPLL) Y2.2
XTIrtc: C12.1 U1.P16(XTIRTC) Y1.4
XTOpll: C13.1 U1.H16(XTOPLL) Y2.1
XTOrtc: C11.1 U1.R17(XTORTC) Y1.1
N17676080: P1.2 U9.13(R1IN)
N17676088: P1.4 P1.6
N17676094: P1.7 P1.8
N17676248: C63.1 U9.1(C1+)
N17676250: C65.1 U9.4(C2+)
N17676258: C64.1 U9.2(V+)
N17676277: C65.2 U9.5(C2-)
N17676279: C63.2 U9.3(C1-)
N17676290: C66.2 U9.6(V-)
N17676296: P1.3 U9.14(TIOUT)
N17676371: P2.3(D+) R26.2 R27.1
N17676373: D6.1 P2.1(VBUS)
N17676393: P2.2(D-) R25.2 R28.1
N17676662: J7.7 U8.3(A1)
N17676664: J7.8 U8.4(A2)
N17676666: J7.9 U8.5(A3)
N17676694: J7.10 U8.6(A4)
N17676696: J7.11 U8.7(A5)
N17676698: J7.12 U8.8(A6)
N17676700: J7.13 U8.9(A7)
N17676702: J7.14 U8.10(A8)
N17676748: J7.6 U10.4(O)
N17678265: DC1.1 SW1.1
N17729965: LED2.1(CATHODE) R13.1
N17729982: LED1.1(CATHODE) R10.1
N17988396: J6.11 R23.1
N18673945: R1.2 U4.19(WP)
N18753883: P3.3(D+) R31.2 R32.2
N19730633: P3.1(VBUS) R33.1
N19761801: F1.2 SW1.2
N19799595: SW2.2 SW2.3 U36.3(nMR)
N19975639: J7.3 R35.1
N20093957: P3.2(D-) R30.2
N20277128: D5.2(ANODE) R22.2

Not connected (* = marked no-connect by the designer): J2 4* 5* 6* 7* 8* 9* 22* 25* 26* 27* 28*; J6 17* 19*; P1 1* 9*; P3 4(ID)* 10(NC1)* 11(NC2)*; SW1 3*; U1 A9(ADDR21/GPA6)* A10(ADDR16/GPA1)* B10(ADDR17/GPA2)* D9(ADDR22/GPA7)* D10(ADDR19/GPA4)* E8(ADDR26/GPA11)* E9(ADDR23/GPA8)* E10(ADDR18/GPA3)* E15(NGCS1/GPA12)* F1(TOUT1/GPB1)* F2(TOUT0/GPB0)* F4(TOUT2/GPB2)* F10(ADDR20/GPA5)* F14(SCLK1)* F17(NGCS7)* G2(NXDACK1/GPB7)* G3(TOUT3/GPB3)* G4(TCLK0/GPB4)* H4(NXDREQ1/GPB8)* L9(EINT11/NSS1/GPG3)* L12(NRTS0/GPH1)* L14(NCTS0/GPH0)* L17(EINT7/GPF7)* N13(AIN7)* R9(EINT14/SPIMOSI1/GPG6)* R10(EINT15/SPICLK1/GPG7)* R12(CLKOUT0/GPH9)* R15(AIN4)* R16(AIN6)* T16(AIN3)* T17(AIN5)* U8(EINT9/GPG1)* U9(EINT13/SPIMISO1/GPG5)* U12(CLKOUT1/GPH10)* U17(AIN2)*; U2 40(NC)*; U3 40(NC)*; U4 1(NC)* 2(NC#2)* 3(NC#3)* 4(NC#4)* 5(NC#5)* 6(NC#6)* 10(NC#10)* 11(NC#11)* 14(NC#14)* 15(NC#15)* 20(NC#20)* 21(NC#21)* 22(NC#22)* 23(NC#23)* 24(NC#24)* 25(NC/VSS)* 26(NC/IO0)* 27(NC/IO8)* 28(NC/IO1)* 33(NC/IO11)* 34(NC#34)* 35(NC#35)* 38(NC#38)* 39(NC#39)* 40(NC/IO4)* 45(NC/IO14)* 46(NC/IO7)* 47(NC/IO15)* 48(NC/VSS#48)*; U9 7(T2OUT)* 8(R2IN)* 9(R2OUT)* 10(T2IN)*; U10 1(NC)*; Y1 2* 3*

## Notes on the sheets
sheet 1
- [JTAG]
- WIZnet Co., Ltd.
- W5300E01-ARM
- Main Processor & JTAG Interface
sheet 2
- Ver 1.0
- USB_D
- USB_H
- P1
- WIZ830MJ
- DC1
- J8
- SW1
- J1
- J2
- J3
- J4
- LCD
- J5
- J6
- J3,4,5 绰 缔搁俊 角厘
- WIZnet  Co., Ltd.
- W5300E01-ARM
- PCB Layout
- WIZnet  Inc.
- W5300E01-ARM
- Main Processor & JTAG Interface
sheet 3
- J8 Jumper 1-2 楷搬矫 16 bit data bus mode
  J8 Jumper 2-3 楷搬矫 8 bit data bus mode
- USB HOST PORT
- L : B -> A
  H : A -> B
- Recommendatory part is 120R@100MHz
- WIZ830MJ
- USB DEVICE PORT
- Recommendatory part is 120R@100MHz
- 2.54mm pitch header (Female)
- [5V DC]
- TAB is Vout
- [ON/OFF]
- WIZnet Co., Ltd.
- W5300E01-ARM
- Memory & I/O Interface & Power
